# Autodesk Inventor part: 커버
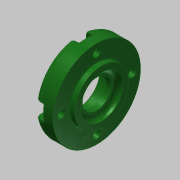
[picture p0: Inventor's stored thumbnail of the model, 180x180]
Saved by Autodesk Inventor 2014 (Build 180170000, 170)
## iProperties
Created: 2015-11
Part Number: 커버
Material: 알루미늄 6061
Document SubType Name: Modeling
Designer: mduedu
Density: 1 g/cm^3
Appearance: 매끄러움 - 짙은 산림 녹색
Author: mduedu
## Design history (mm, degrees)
sketch "스케치1"
  geometry: L1 (-7, 0)-(7, 0); L2 (-7, 0)-(-7, 26); L3 (-7, 26)-(4, 26); L4 (4, 26)-(4, 16); L5 (4, 16)-(7, 16); L6 (7, 16)-(7, 0); 2 further points
  constraints: 12 end point, 3 perpendicular, 2 parallel, 1 coincident, 1 horizontal, 1 midpoint
  dimensions: "d0" = 14 distance of L1.start L1.end; "d1" = 52 diameter of L3 L1; "d2" = 3 distance of L4.end L5.end; "d3" = 32 diameter of L5 L1
revolve "회전1" sketch "스케치1" stored, may be unused: angle "d4" = 90 deg
hole "구멍1" diameter "d7" = 25; stored, may be unused: countersink angle "d11" = 90 deg, drill point angle "d13" = 0 deg; dims "d5" = 10, "d6" = 10, "d8" = 6, "d9" = 4, "d10" = 2, "d12" = 3
hole "구멍2" diameter "d16" = 25; stored, may be unused: countersink angle "d20" = 90 deg, drill point angle "d22" = 0 deg; dims "d17" = 6, "d18" = 4, "d19" = 2, "d21" = 7.7, "d58" = 10, "d59" = 10
hole "구멍3" diameter "d25" = 17; stored, may be unused: countersink angle "d29" = 90 deg, drill point angle "d31" = 0 deg; dims "d23" = 10, "d24" = 10, "d26" = 6, "d27" = 4, "d28" = 2, "d30" = 4.2
chamfer "모따기1" distance "d32" = 0.6; stored, may be unused: second distance "d33" = 2, angle "d34" = 30 deg
fillet "모깎기1" dims "d35" = 0.3
fillet "모깎기2" dims "d36" = 3
fillet "모깎기3" dims "d37" = 3
fillet "모깎기4" dims "d38" = 0.3
sketch "스케치3" dims "d61" = 42
  geometry: C1 r 26 at (0, 0) reference; 2 further points
  constraints: 2 vertical alignment, 1 coincident, 2 other
hole "구멍4" sketch "스케치3" at (0, -21) diameter "d44" = 4.5; stored, may be unused: countersink angle "d48" = 90 deg, drill point angle "d50" = 0 deg; dims "d45" = 6, "d46" = 8, "d47" = 4.6, "d49" = 8
sketch "스케치4"
  geometry: L1 (-4, 0)-(-4, -4.69); L2 (4, 0)-(4, -4.69); A1 r 4 centre (0, 0) between (3.614, -1.714) and (-3.614, -1.714) reference; A2 r 26 centre (0, 21) between (-4, -4.69) and (4, -4.69) reference; 1 further point
  constraints: 4 end point, 4 point on circle, 2 tangent, 1 parallel, 1 vertical
extrude "돌출1" cut sketch "스케치4" stored distance "d51" = 0; taper "d52" = 0 deg
fillet "모깎기5" dims "d56" = 0.3
fillet "모깎기6" dims "d57" = 1
node "솔리드1"
pattern_circular "원형 패턴1" dims angle "d54" = 360 deg
